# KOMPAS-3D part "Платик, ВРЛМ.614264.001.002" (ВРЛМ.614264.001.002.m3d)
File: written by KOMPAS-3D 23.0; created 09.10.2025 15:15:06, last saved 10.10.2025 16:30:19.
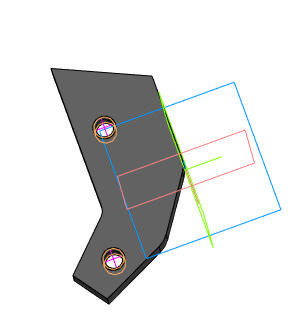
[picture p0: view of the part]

Document properties: Автор: EmelyanenkoEY; Полное имя файла: ВРЛМ.614264.001.002.cdw

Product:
- Part/product: Платик  | designation ВРЛМ.614264.001.002
    Материал: Сталь 03Х17Н14М3 ГОСТ 5632-2014 (density 8000 kg/m3)
    Масса: 0.156981
    Форматы листов документа: A3

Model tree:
1. Эскиз:1
2. Элемент выдавливания:1
     Расстояние 1 = 8
3. Скругление:1  (with: Элемент выдавливания:1)
     Радиус = 10
4. Скругление:2  (with: Элемент выдавливания:1)
     Радиус = 10
5. Скругление:3  (with: Элемент выдавливания:1)
     Радиус = 5
6. Эскиз:2  (with: Элемент выдавливания:1)
7. Эскиз:3  (with: Элемент выдавливания:1)
8. Отверстие:1  (with: Элемент выдавливания:1)  (labels: M8)
     Глубина выреза = 8; Диаметр отверстия = 6.64684; Угол конуса дна = 118; Расстояние 1 = -13.3523; Расстояние 2 = 52.3308
9. M8  (with: Отверстие:1, Элемент выдавливания:1)  (labels: cil0_24705-2004 coarse)
     Длина резьбы = 8; Шаг резьбы = 1.25; Номинальный диаметр резьбы = 8
10. Отверстие:2  (with: Элемент выдавливания:1, M8)  (labels: M8; cil0_24705-2004 coarse)
     Глубина выреза = 8; Диаметр отверстия = 6.64684; Угол конуса дна = 118; Расстояние 1 = 10.9582; Расстояние 2 = 13.602; Длина резьбы = 8; Шаг резьбы = 1.25; Номинальный диаметр резьбы = 8
11. Фаска:1  (with: Отверстие:2)
     Угол = 45; Длина 1 = 1; Длина 2 = 1
12. Фаска:2  (with: Отверстие:1, Отверстие:2)  (labels: Сталь 03Х17Н14М3 ГОСТ 5632-2014; BOSimple***Material:eb0a4e4c-f881-4f25-af2f-9f38547546d4)
     Угол = 45; Длина 1 = 1; Длина 2 = 1

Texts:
  ВРЛМ.614264.001.002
